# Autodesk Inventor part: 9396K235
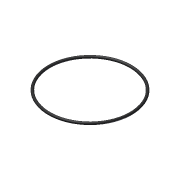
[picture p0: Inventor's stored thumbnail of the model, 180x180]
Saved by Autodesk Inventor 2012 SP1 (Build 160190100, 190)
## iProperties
Created: 2012-03
Part Number: 9396K235
Material: Silicone
Document SubType Name: Modeling
Designer: jdh
Mass: 4.39238 g
Surface Area: 39.8108 cm^2
Volume: 3.5139 cm^3
Density: 1.25 g/cm^3
Author: jdh
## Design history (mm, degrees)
sketch "Sketch1"
  geometry: L1 (-58.89, 1.765)-(-55.359, 1.765); L2 (-55.359, 1.765)-(-55.359, -1.765); L3 (-55.359, -1.765)-(-58.89, -1.765); L4 (-58.89, -1.765)-(-58.89, 1.765); L5 (-57.125, 0)-(0, 0); L6 (0, -2.471)-(0, 2.471) reference; C1 r 1.765 at (-57.125, 0)
  constraints: 10 end point, 4 tangent, 2 horizontal, 2 parallel, 1 centre point, 1 perpendicular
  dimensions: "d0" = 58.8899 distance from line of L5.end L4; "d1" = 55.3593 distance from line of L5.end L2
revolve "Revolution1" sketch "Sketch1" stored, may be unused: angle "d2" = 90 deg
body "Solid1"
